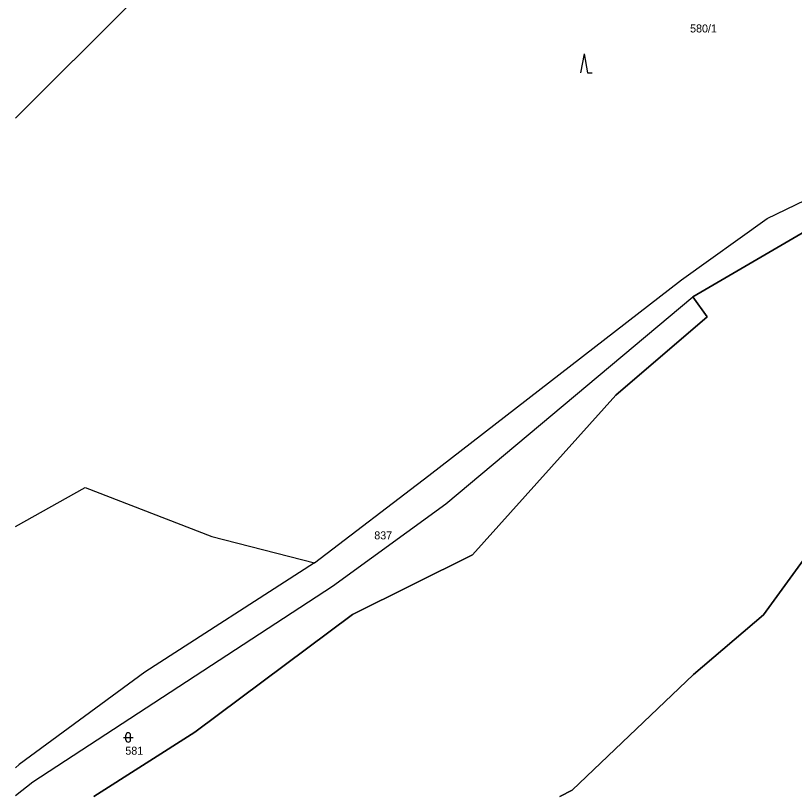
# Model space of a CAD drawing. Extents: x -737240 to -735272, y -1119606 to -1117878.
# Drawn here: x -737233.3 to -737068, y -1119605.2 to -1119439.5 of the extents above; entities that cross this region are included whole.
import ezdxf

# ---------------------------------------------------------------- set-up
doc = ezdxf.new("R2010")
doc.units = 0
for name, color, linetype in [('Level 1', 7, 'Continuous'), ('Level 13', 7, 'Continuous'), ('Level 18', 7, 'Continuous'), ('Level 25', 7, 'Continuous')]:
    doc.layers.add(name, color=color, linetype=linetype)

msp = doc.modelspace()

# ---------------------------------------------------------------- linework, layer by layer
at = {"layer": 'Level 1'}
msp.add_line((-737208.77, -1119436.8), (-737233.313, -1119461.283), dxfattribs=at)
for points in [[(-737169.84, -1119555.71), (-737145.58, -1119537.17), (-737091.98, -1119495.63), (-737073.74, -1119482.62), (-737059.54, -1119475.74), (-737014.71, -1119462.57), (-736984.4, -1119460.93), (-736944.65, -1119465.48), (-736927.41, -1119472.39)], [(-737216.715, -1119605.245), (-737195.3, -1119591.61), (-737161.79, -1119566.64), (-737136.35, -1119553.97), (-737105.92, -1119520.12), (-737086.52, -1119503.45), (-737089.51, -1119499.2), (-737057.31, -1119480.43), (-737014.04, -1119467.4), (-736983.65, -1119466.42), (-736946.02, -1119471.12), (-736913.05, -1119484.42)], [(-736910.16, -1119479.31), (-736913.05, -1119484.42), (-736946.02, -1119471.12), (-736983.65, -1119466.42), (-737014.04, -1119467.4), (-737057.31, -1119480.43), (-737089.51, -1119499.2)], [(-737233.313, -1119605.031), (-737229.68, -1119602.15), (-737166.05, -1119560.65), (-737141.95, -1119543.14), (-737089.51, -1119499.2)], [(-737089.51, -1119499.2), (-737086.52, -1119503.45), (-737105.92, -1119520.12), (-737136.35, -1119553.97), (-737161.79, -1119566.64), (-737195.3, -1119591.61), (-737216.715, -1119605.245)], [(-736846.288, -1119605.245), (-736861.5, -1119587.54), (-736876.45, -1119570.44), (-736915.59, -1119539.71), (-736958.37, -1119516.8), (-736990.95, -1119509.95), (-737035.14, -1119521.71), (-737062.63, -1119550.39), (-737074.57, -1119566.7), (-737089.38, -1119579.37), (-737115.15, -1119603.93), (-737117.805, -1119605.245)], [(-737117.805, -1119605.245), (-737115.15, -1119603.93), (-737089.38, -1119579.37), (-737074.57, -1119566.7), (-737062.63, -1119550.39), (-737035.14, -1119521.71), (-736990.95, -1119509.95), (-736958.37, -1119516.8), (-736915.59, -1119539.71), (-736876.45, -1119570.44), (-736861.5, -1119587.54), (-736846.288, -1119605.245)], [(-737233.313, -1119547.941), (-737218.53, -1119539.67), (-737191.67, -1119550.08), (-737169.84, -1119555.71)], [(-737169.84, -1119555.71), (-737205.91, -1119578.9), (-737232.53, -1119598.51), (-737233.313, -1119599.156)]]:
    msp.add_lwpolyline(points, dxfattribs=at)
at = {"layer": 'Level 13'}
for points in [[(-736821.33, -1119373.76), (-736848.42, -1119373.24), (-736854.28, -1119371.68), (-736862.02, -1119369.61), (-736873.66, -1119366.5), (-736885.97, -1119404.55), (-736910.16, -1119479.31), (-736913.05, -1119484.42), (-736946.02, -1119471.12), (-736983.65, -1119466.42), (-737014.04, -1119467.4), (-737057.31, -1119480.43), (-737089.51, -1119499.2), (-737086.52, -1119503.45), (-737105.92, -1119520.12), (-737136.35, -1119553.97), (-737161.79, -1119566.64), (-737195.3, -1119591.61), (-737216.715, -1119605.245)], [(-736821.33, -1119373.76), (-736848.42, -1119373.24), (-736854.28, -1119371.68), (-736862.02, -1119369.61), (-736873.66, -1119366.5), (-736885.97, -1119404.55), (-736910.16, -1119479.31), (-736913.05, -1119484.42), (-736946.02, -1119471.12), (-736983.65, -1119466.42), (-737014.04, -1119467.4), (-737057.31, -1119480.43), (-737089.51, -1119499.2), (-737086.52, -1119503.45), (-737105.92, -1119520.12), (-737136.35, -1119553.97), (-737161.79, -1119566.64), (-737195.3, -1119591.61), (-737216.715, -1119605.245)], [(-736846.288, -1119605.245), (-736861.5, -1119587.54), (-736876.45, -1119570.44), (-736915.59, -1119539.71), (-736958.37, -1119516.8), (-736990.95, -1119509.95), (-737035.14, -1119521.71), (-737062.63, -1119550.39), (-737074.57, -1119566.7), (-737089.38, -1119579.37), (-737115.15, -1119603.93), (-737117.805, -1119605.245)], [(-737117.805, -1119605.245), (-737115.15, -1119603.93), (-737089.38, -1119579.37), (-737074.57, -1119566.7), (-737062.63, -1119550.39), (-737035.14, -1119521.71), (-736990.95, -1119509.95), (-736958.37, -1119516.8), (-736915.59, -1119539.71), (-736876.45, -1119570.44), (-736861.5, -1119587.54), (-736846.288, -1119605.245)]]:
    msp.add_lwpolyline(points, dxfattribs=at)
at = {"layer": 'Level 25'}
for p, q in [((-737112.642, -1119447.669), (-737113.375, -1119451.669)), ((-737112.642, -1119447.669), (-737111.909, -1119451.669)), ((-737111.909, -1119451.669), (-737110.909, -1119451.669)), ((-737209.89, -1119593.23), (-737209.89, -1119592.23)), ((-737208.89, -1119593.23), (-737208.89, -1119592.23)), ((-737210.39, -1119592.73), (-737208.39, -1119592.73))]:
    msp.add_line(p, q, dxfattribs=at)
for centre, start, end in [((-737209.39, -1119592.23), 0, 180), ((-737209.39, -1119593.23), 180, 0)]:
    msp.add_arc(centre, 0.5, start, end, dxfattribs=at)

# ---------------------------------------------------------------- texts
at = {"layer": 'Level 18'}
for s, p in [('580/1', (-737090.125, -1119443.11)), ('837', (-737157.17, -1119550.7)), ('581', (-737210.02, -1119596.4))]:
    msp.add_text(s, height=1.7, dxfattribs=at).set_placement(p)

doc.saveas('drawing.dxf')
